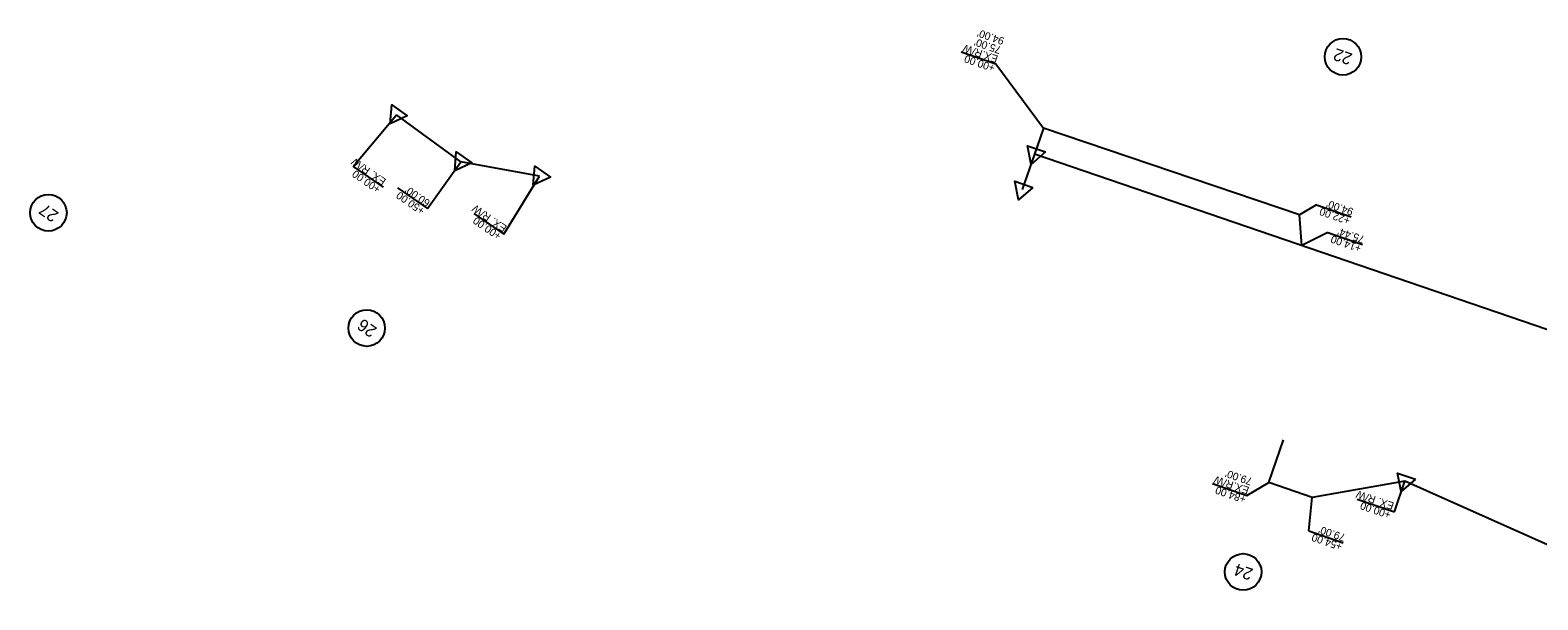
# Model space of a CAD drawing. Extents: x 474184 to 481900, y 489262 to 505659.
# Drawn here: x 479338 to 480329, y 493245 to 493620 of the extents above; entities that cross this region are included whole.
import ezdxf

# ---------------------------------------------------------------- set-up
doc = ezdxf.new("R2010")
doc.units = 0
for name, color, linetype in [('Prop Drainage Structure Drop Inlet Grate 2 Narrow Slots and Sag Grates 840 24 CELL', 7, 'Continuous'), ('Prop Drainage Structure Outlet Berm Ditch 850 10 CELL', 7, 'Continuous'), ('Prop Drainage Structure Pipe CSP 15in', 7, 'Continuous'), ('Prop Drainage Structure Pipe RCP 18in Class IV', 7, 'Continuous'), ('Prop Drainage Structure Pipe Side Drain 15in Label', 7, 'Continuous'), ('Prop Drainage Structure Pipe Stub Out CELL', 7, 'Continuous'), ('Prop Drainage Structure Plot Symbol 50 Scale', 7, 'Continuous'), ('Prop Earthen Structure False Sump Label', 7, 'Continuous')]:
    doc.layers.add(name, color=color, linetype=linetype)

msp = doc.modelspace()

# ---------------------------------------------------------------- linework, layer by layer
at = {"layer": 'Prop Drainage Structure Drop Inlet Grate 2 Narrow Slots and Sag Grates 840 24 CELL'}
for p, q in [((480004.02, 493555.58), (479998.09, 493538.59)), ((480172.05, 493498.53), (480004.02, 493555.58)), ((480173.59, 493478.39), (480172.05, 493498.53))]:
    msp.add_line(p, q, dxfattribs=at)
at = {"layer": 'Prop Drainage Structure Outlet Berm Ditch 850 10 CELL'}
for p, q in [((479949.93, 493605.76), (479972.67, 493597.93)), ((480183.32, 493505.15), (480206.06, 493497.32)), ((480190.71, 493486.96), (480213.44, 493479.12))]:
    msp.add_line(p, q, dxfattribs=at)
for points in [[(479972.67, 493597.93), (480004.02, 493555.58)], [(480183.32, 493505.15), (480172.05, 493498.53)], [(480190.71, 493486.96), (480173.59, 493478.39)]]:
    msp.add_lwpolyline(points, dxfattribs=at)
at = {"layer": 'Prop Drainage Structure Pipe CSP 15in'}
for p, q in [((480200.65, 493602.51), (480200.65, 493602.51)), ((479350.24, 493499.96), (479350.24, 493499.96)), ((479559.34, 493424.15), (479559.34, 493424.15)), ((480135.1, 493263.86), (480135.1, 493263.86))]:
    msp.add_line(p, q, dxfattribs=at)
for centre in [(480200.65, 493602.51), (479350.24, 493499.96), (479559.34, 493424.15), (480135.1, 493263.86)]:
    msp.add_circle(centre, 12, dxfattribs=at)
at = {"layer": 'Prop Drainage Structure Pipe RCP 18in Class IV'}
for p, q in [((479578.81, 493564.36), (479578.81, 493564.36)), ((479998.09, 493538.59), (479998.09, 493538.59)), ((479621.25, 493533.48), (479621.25, 493533.48)), ((479672.92, 493524.07), (479672.92, 493524.07)), ((479989.94, 493515.25), (479989.94, 493515.25)), ((480241.25, 493323.45), (480241.25, 493323.45))]:
    msp.add_line(p, q, dxfattribs=at)
for points in [[(479574.68, 493558.45), (479575.75, 493570.88), (479586, 493563.76)], [(479617.12, 493527.57), (479618.2, 493540), (479628.44, 493532.88)], [(480005.17, 493539.96), (479995.74, 493531.78), (479993.35, 493544.03)], [(479668.79, 493518.15), (479669.87, 493530.59), (479680.11, 493523.46)], [(479997.02, 493516.62), (479987.59, 493508.44), (479985.2, 493520.69)], [(480248.33, 493324.81), (480238.9, 493316.64), (480236.51, 493328.88)]]:
    msp.add_lwpolyline(points, close=True, dxfattribs=at)
at = {"layer": 'Prop Drainage Structure Pipe Side Drain 15in Label'}
for p, q in [((479998.09, 493538.59), (479989.94, 493515.25)), ((480527.66, 493356.94), (479998.09, 493538.59)), ((480415.91, 493245.48), (480241.25, 493323.45))]:
    msp.add_line(p, q, dxfattribs=at)
msp.add_lwpolyline([(479672.92, 493524.07), (479621.25, 493533.48), (479578.81, 493564.36)], dxfattribs=at)
at = {"layer": 'Prop Drainage Structure Pipe Stub Out CELL'}
for p, q in [((480152.04, 493322.54), (480161.65, 493350.71)), ((480180.51, 493312.84), (480152.04, 493322.54)), ((480241.25, 493323.45), (480180.51, 493312.84))]:
    msp.add_line(p, q, dxfattribs=at)
at = {"layer": 'Prop Drainage Structure Plot Symbol 50 Scale'}
for p, q in [((479550.42, 493530.47), (479570.18, 493516.77)), ((479579.48, 493516.45), (479599.24, 493502.75)), ((479629.66, 493499.55), (479649.42, 493485.85)), ((480210.01, 493311.66), (480234.42, 493303.25))]:
    msp.add_line(p, q, dxfattribs=at)
for points in [[(479550.42, 493530.47), (479578.81, 493564.36)], [(479599.24, 493502.75), (479621.25, 493533.48)], [(479649.42, 493485.85), (479672.92, 493524.07)], [(480234.42, 493303.25), (480241.25, 493323.45)]]:
    msp.add_lwpolyline(points, dxfattribs=at)
at = {"layer": 'Prop Earthen Structure False Sump Label'}
for p, q in [((480114.88, 493321.95), (480137.62, 493314.11)), ((480178.17, 493290.9), (480200.9, 493283.07))]:
    msp.add_line(p, q, dxfattribs=at)
for points in [[(480137.62, 493314.11), (480152.04, 493322.54)], [(480178.17, 493290.9), (480180.51, 493312.84)]]:
    msp.add_lwpolyline(points, dxfattribs=at)

# ---------------------------------------------------------------- texts
at = {"layer": 'Prop Drainage Structure Outlet Berm Ditch 850 10 CELL'}
for s, p in [("75.00'", (479976.54, 493608.97)), ("94.00' ", (479978.57, 493614.88)), ('EX.R/W', (479974.5, 493603.06)), ('+00.00', (479972.47, 493597.15)), ("94.00'", (480207.89, 493502.64)), ('+22.00', (480205.85, 493496.73)), ("75.44'", (480215.27, 493484.44)), ('+14.00', (480213.24, 493478.53))]:
    msp.add_text(s, height=5, rotation=160.98924, dxfattribs=at).set_placement(p)
at = {"layer": 'Prop Drainage Structure Pipe CSP 15in'}
for s, rotation, p in [('22', 160.98924, (480207.42, 493604.41)), ('27', 145.2516, (479357.52, 493499.78)), ('26', 145.2516, (479566.62, 493423.97)), ('24', 160.98924, (480142.16, 493265.66))]:
    msp.add_text(s, height=8, rotation=rotation, dxfattribs=at).set_placement(p)
at = {"layer": 'Prop Drainage Structure Plot Symbol 50 Scale'}
for s, rotation, p in [('EX. R/W', 145.2516, (479572.52, 493521.75)), ('+00.00', 145.2516, (479568.96, 493516.62)), ("60.00'", 145.2516, (479601.49, 493507.61)), ('+50.00', 145.2516, (479597.93, 493502.48)), ('EX. R/W', 145.2516, (479651.88, 493491.03)), ('+00.00', 145.2516, (479648.32, 493485.9)), ('EX. R/W', 160.98924, (480234.62, 493309.26)), ('+00.00', 160.98924, (480232.58, 493303.35))]:
    msp.add_text(s, height=5, rotation=rotation, dxfattribs=at).set_placement(p)
at = {"layer": 'Prop Earthen Structure False Sump Label'}
for s, p in [('EX.R/W', (480139.45, 493319.43)), ("79.00'", (480141.48, 493325.34)), ('+84.00', (480137.41, 493313.52)), ('+54.00', (480200.7, 493282.48)), ("79.00'", (480202.74, 493288.39))]:
    msp.add_text(s, height=5, rotation=160.995, dxfattribs=at).set_placement(p)

doc.saveas('drawing.dxf')
